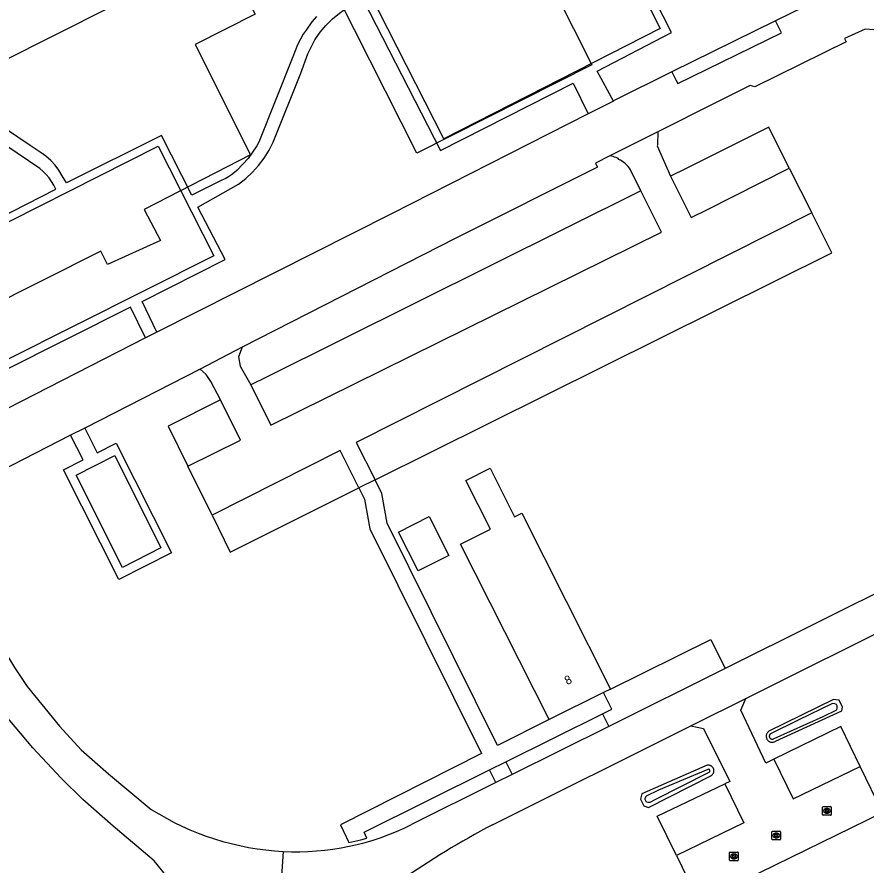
# Model space of a CAD drawing. Extents: x 158132 to 159658, y 385257 to 387209.
# Drawn here: x 159064.7 to 159162.7, y 386283.7 to 386381.6 of the extents above; entities that cross this region are included whole.
import ezdxf

# ---------------------------------------------------------------- set-up
doc = ezdxf.new("R2010")
doc.units = 0
for name, color, linetype in [('IMGEO_Groenvoorziening', 7, 'Continuous'), ('IMGEO_Kolk', 7, 'Continuous'), ('IMGEO_Pand', 7, 'Continuous'), ('IMGEO_Pand_nummerreeks', 7, 'Continuous'), ('IMGEO_Pand_vergunning_verleend', 7, 'Continuous'), ('IMGEO_Parkeervlak_halfverhard', 7, 'Continuous'), ('IMGEO_Parkeervlak_open', 7, 'Continuous'), ('IMGEO_Rijbaan_lokaal_gesloten', 7, 'Continuous'), ('IMGEO_Rijbaan_lokaal_open', 7, 'Continuous'), ('IMGEO_Voetpad_open', 7, 'Continuous'), ('IMGEO_Waterloop', 7, 'Continuous')]:
    doc.layers.add(name, color=color, linetype=linetype)

msp = doc.modelspace()

# ---------------------------------------------------------------- linework, layer by layer
at = {"layer": 'IMGEO_Groenvoorziening'}
for points in [[(159158.798, 386302.932), (159151.341, 386299.282), (159151.292, 386299.246), (159151.247, 386299.206), (159151.205, 386299.162), (159151.167, 386299.115), (159151.133, 386299.065), (159151.104, 386299.012), (159151.08, 386298.957), (159151.06, 386298.9), (159151.045, 386298.841), (159151.036, 386298.781), (159151.032, 386298.721), (159151.033, 386298.66), (159151.039, 386298.6), (159151.051, 386298.541), (159151.067, 386298.482), (159151.089, 386298.426), (159151.116, 386298.372), (159151.147, 386298.32), (159151.182, 386298.271), (159151.222, 386298.225), (159151.265, 386298.183), (159151.312, 386298.145), (159151.362, 386298.111), (159151.415, 386298.081), (159151.47, 386298.057), (159151.527, 386298.037), (159151.586, 386298.022), (159151.646, 386298.012), (159151.706, 386298.008), (159151.767, 386298.009), (159151.827, 386298.015), (159151.886, 386298.026), (159151.945, 386298.042), (159152.001, 386298.064), (159152.056, 386298.09), (159152.108, 386298.121), (159159.754, 386301.623), (159159.831, 386302.052), (159159.448, 386302.852), (159158.798, 386302.932)], [(159144.994, 386294.836), (159144.981, 386294.891), (159144.964, 386294.944), (159144.942, 386294.996), (159144.916, 386295.045), (159144.885, 386295.093), (159144.851, 386295.137), (159144.812, 386295.178), (159144.771, 386295.215), (159144.726, 386295.249), (159144.678, 386295.279), (159144.628, 386295.305), (159144.576, 386295.326), (159144.523, 386295.342), (159144.468, 386295.354), (159144.412, 386295.36), (159144.356, 386295.362), (159144.3, 386295.359), (159144.244, 386295.351), (159136.707, 386292.056), (159136.523, 386291.463), (159136.925, 386290.7), (159137.467, 386290.481), (159144.636, 386294.139), (159144.686, 386294.165), (159144.733, 386294.196), (159144.777, 386294.23), (159144.818, 386294.268), (159144.856, 386294.31), (159144.89, 386294.355), (159144.92, 386294.402), (159144.946, 386294.452), (159144.967, 386294.504), (159144.983, 386294.558), (159144.995, 386294.612), (159145.002, 386294.668), (159145.004, 386294.724), (159145.001, 386294.78), (159144.994, 386294.836)]]:
    msp.add_lwpolyline(points, dxfattribs=at)
at = {"layer": 'IMGEO_Kolk'}
for p, q in [((159157.534, 386289.676), (159157.534, 386290.528)), ((159157.609, 386290.602), (159158.461, 386290.602)), ((159158.022, 386290.382), (159158.047, 386290.382)), ((159158.535, 386290.528), (159158.535, 386289.676)), ((159158.461, 386289.602), (159157.609, 386289.602)), ((159158.045, 386289.822), (159158.02, 386289.822)), ((159151.694, 386286.836), (159151.694, 386287.688)), ((159151.769, 386287.762), (159152.621, 386287.762)), ((159152.182, 386287.542), (159152.207, 386287.542)), ((159152.695, 386287.688), (159152.695, 386286.836)), ((159152.621, 386286.762), (159151.769, 386286.762)), ((159152.205, 386286.982), (159152.18, 386286.982)), ((159146.813, 386284.434), (159146.813, 386285.286)), ((159146.888, 386285.36), (159147.74, 386285.36)), ((159147.324, 386284.58), (159147.299, 386284.58)), ((159147.301, 386285.14), (159147.326, 386285.14)), ((159147.814, 386285.286), (159147.814, 386284.434)), ((159147.74, 386284.36), (159146.888, 386284.36))]:
    msp.add_line(p, q, dxfattribs=at)
for points in [[(159157.534, 386289.676), (159157.534, 386290.528)], [(159157.609, 386290.602), (159158.461, 386290.602)], [(159158.535, 386290.528), (159158.535, 386289.676)], [(159158.461, 386289.602), (159157.609, 386289.602)], [(159157.855, 386290.302), (159157.978, 386290.302), (159157.978, 386290.151), (159158.108, 386290.302), (159158.272, 386290.302), (159158.126, 386290.151), (159158.279, 386289.902), (159158.127, 386289.902), (159158.042, 386290.066), (159157.978, 386289.999), (159157.978, 386289.902), (159157.855, 386289.902), (159157.855, 386290.302)], [(159151.694, 386286.836), (159151.694, 386287.688)], [(159151.769, 386287.762), (159152.621, 386287.762)], [(159152.015, 386287.462), (159152.138, 386287.462), (159152.138, 386287.311), (159152.268, 386287.462), (159152.432, 386287.462), (159152.286, 386287.311), (159152.439, 386287.062), (159152.287, 386287.062), (159152.202, 386287.226), (159152.138, 386287.159), (159152.138, 386287.062), (159152.015, 386287.062), (159152.015, 386287.462)], [(159152.695, 386287.688), (159152.695, 386286.836)], [(159152.621, 386286.762), (159151.769, 386286.762)], [(159146.813, 386284.434), (159146.813, 386285.286)], [(159146.888, 386285.36), (159147.74, 386285.36)], [(159147.134, 386285.06), (159147.257, 386285.06), (159147.257, 386284.909), (159147.387, 386285.06), (159147.551, 386285.06), (159147.405, 386284.909), (159147.558, 386284.66), (159147.406, 386284.66), (159147.321, 386284.824), (159147.257, 386284.757), (159147.257, 386284.66), (159147.134, 386284.66), (159147.134, 386285.06)], [(159147.814, 386285.286), (159147.814, 386284.434)], [(159147.74, 386284.36), (159146.888, 386284.36)]]:
    msp.add_lwpolyline(points, dxfattribs=at)
for centre, start, end in [((159157.611, 386290.526), 91.55205, 178.44795), ((159157.611, 386290.526), 91.55205, 178.44795), ((159158.459, 386290.526), 1.55205, 88.44795), ((159158.459, 386290.526), 1.55205, 88.44795), ((159157.611, 386289.678), 181.55205, 268.44795), ((159157.611, 386289.678), 181.55205, 268.44795), ((159158.459, 386289.678), 271.55205, 358.44795), ((159158.459, 386289.678), 271.55205, 358.44795), ((159151.771, 386287.686), 91.55205, 178.44795), ((159151.771, 386287.686), 91.55205, 178.44795), ((159152.619, 386287.686), 1.55205, 88.44795), ((159152.619, 386287.686), 1.55205, 88.44795), ((159151.771, 386286.838), 181.55205, 268.44795), ((159151.771, 386286.838), 181.55205, 268.44795), ((159152.619, 386286.838), 271.55205, 358.44795), ((159152.619, 386286.838), 271.55205, 358.44795), ((159146.89, 386285.284), 91.55205, 178.44795), ((159146.89, 386285.284), 91.55205, 178.44795), ((159147.738, 386285.284), 1.55205, 88.44795), ((159147.738, 386285.284), 1.55205, 88.44795), ((159146.89, 386284.436), 181.55205, 268.44795), ((159146.89, 386284.436), 181.55205, 268.44795), ((159147.738, 386284.436), 271.55205, 358.44795), ((159147.738, 386284.436), 271.55205, 358.44795)]:
    msp.add_arc(centre, 0.0765, start, end, dxfattribs=at)
for centre, major_axis, ratio, start_param, end_param in [((159158.021, 386290.102), (-0.387, 0.002), 0.722429, 4.712389, 7.853982), ((159158.046, 386290.102), (-0.39, 0.002), 0.717154, 1.570796, 4.712389), ((159152.181, 386287.262), (-0.387, 0.002), 0.722429, 4.712389, 7.853982), ((159152.206, 386287.262), (-0.39, 0.002), 0.717154, 1.570796, 4.712389), ((159147.3, 386284.86), (-0.387, 0.002), 0.722429, 4.712389, 7.853982), ((159147.325, 386284.86), (-0.39, 0.002), 0.717154, 1.570796, 4.712389)]:
    msp.add_ellipse(centre, major_axis=major_axis, ratio=ratio, start_param=start_param, end_param=end_param, dxfattribs=at)
at = {"layer": 'IMGEO_Pand'}
for points in [[(159075.958, 386331.045), (159081.256, 386320.404), (159076.815, 386318.132), (159071.496, 386328.786), (159075.958, 386331.045)], [(159126.002, 386300.637), (159115.808, 386320.841), (159119.244, 386322.574), (159116.412, 386328.188), (159119.201, 386329.595), (159122.033, 386323.981), (159122.863, 386324.4), (159133.085, 386304.138)], [(159114.449, 386319.54), (159110.896, 386317.747), (159108.63, 386322.237), (159112.184, 386324.031), (159114.449, 386319.54)], [(159133.085, 386304.138), (159132.291, 386303.745)], [(159132.291, 386303.745), (159126.002, 386300.637)]]:
    msp.add_lwpolyline(points, dxfattribs=at)
at = {"layer": 'IMGEO_Pand_vergunning_verleend'}
msp.add_lwpolyline([(159050.566, 386368.036), (159057.316, 386371.439), (159056.434, 386373.19), (159088.099, 386389.152), (159085.805, 386393.704), (159116.592, 386409.224), (159123.517, 386395.487), (159125.076, 386396.273), (159128.071, 386390.332), (159124.613, 386388.589), (159130.927, 386376.065), (159110.742, 386365.89), (159098.147, 386390.876), (159089.73, 386386.633), (159092.108, 386381.915), (159085.183, 386378.425), (159091.591, 386365.714), (159079.324, 386359.397), (159081.204, 386355.823), (159075.094, 386353.069), (159074.314, 386354.616), (159060.772, 386347.79), (159050.566, 386368.036)], dxfattribs=at)
at = {"layer": 'IMGEO_Parkeervlak_halfverhard'}
for points in [[(159153.697, 386364.175), (159151.323, 386368.887), (159141.789, 386364.145), (159140.014, 386363.262)], [(159136.589, 386361.558), (159093.441, 386340.095), (159091.613, 386339.186)], [(159105.953, 386328.242), (159158.608, 386354.428), (159156.297, 386359.015)], [(159088.141, 386337.458), (159082.079, 386334.443), (159084.365, 386329.818)], [(159087.154, 386324.178), (159089.251, 386319.936), (159104.088, 386327.315)]]:
    msp.add_lwpolyline(points, dxfattribs=at)
at = {"layer": 'IMGEO_Parkeervlak_open'}
for points in [[(159161.883, 386295.226), (159159.646, 386299.844), (159151.929, 386296.073)], [(159140.694, 386284.963), (159138.479, 386289.495), (159146.258, 386293.231)]]:
    msp.add_lwpolyline(points, dxfattribs=at)
at = {"layer": 'IMGEO_Rijbaan_lokaal_gesloten'}
for points in [[(159160.679, 386385.483), (159159.095, 386384.711), (159156.975, 386383.586), (159152.098, 386381.168)], [(159140.172, 386375.255), (159140.617, 386374.368), (159140.838, 386373.928), (159152.778, 386379.783), (159152.098, 386381.168)], [(159163.452, 386380.131), (159162.434, 386380.179), (159160.052, 386379.107), (159160.256, 386378.722), (159149.707, 386373.549), (159149.172, 386373.703), (159145.189, 386371.704), (159138.555, 386368.375)], [(159140.172, 386375.255), (159133.433, 386371.914), (159133.41, 386371.902)], [(159133.41, 386371.902), (159130.505, 386370.426)], [(159130.505, 386370.426), (159107.817, 386358.895), (159080.782, 386345.286)], [(159138.555, 386368.375), (159133.011, 386365.593)], [(159133.011, 386365.593), (159131.347, 386364.73), (159131.513, 386364.412), (159131.574, 386364.295), (159115.248, 386356.119), (159090.616, 386343.54)], [(159080.782, 386345.286), (159079.47, 386344.616)], [(159079.47, 386344.616), (159061.863, 386335.619), (159057.491, 386333.552), (159057.754, 386333.009), (159056.795, 386332.597), (159056.135, 386332.455), (159055.464, 386332.371), (159054.789, 386332.347), (159054.115, 386332.381), (159053.446, 386332.474), (159052.787, 386332.626), (159052.145, 386332.834), (159051.523, 386333.098), (159050.927, 386333.415), (159050.36, 386333.783), (159049.828, 386334.199), (159049.335, 386334.66), (159048.883, 386335.163), (159048.542, 386335.617)], [(159090.616, 386343.54), (159085.768, 386341.008)], [(159085.768, 386341.008), (159072.465, 386334.219)], [(159072.465, 386334.219), (159070.847, 386333.393)], [(159070.847, 386333.393), (159061.295, 386328.518), (159060.937, 386329.18), (159060.892, 386329.157)], [(159105.953, 386328.242), (159104.088, 386327.315)], [(159126.002, 386300.637), (159120.07, 386297.644), (159107.337, 386323.246), (159106.738, 386326.663), (159105.953, 386328.242)], [(159104.088, 386327.315), (159104.739, 386326.006), (159105.338, 386322.589), (159118.21, 386296.706), (159101.95, 386288.501), (159102.935, 386286.444), (159103.626, 386286.599), (159104.313, 386286.771), (159104.996, 386286.96), (159104.695, 386287.635), (159119.145, 386294.827)], [(159187.744, 386327.14), (159146.313, 386306.52)], [(159148.667, 386303.059), (159186.019, 386321.678), (159190.748, 386323.367), (159191.885, 386323.216)], [(159057.062, 386320.945), (159063.133, 386308.664), (159064.373, 386306.618), (159065.843, 386304.447), (159069.55, 386299.848), (159072.072, 386297.131), (159075.195, 386294.366), (159080.133, 386290.273)], [(159083.086, 386281.447), (159081.827, 386282.687), (159080.46, 386284.342), (159075.757, 386288.34), (159072.25, 386291.429), (159069.75, 386293.857), (159066.469, 386297.371), (159062.371, 386302.202), (159058.593, 386308.797), (159053.255, 386319.337)], [(159146.313, 386306.52), (159132.873, 386299.831)], [(159132.148, 386301.298), (159133.233, 386301.839), (159132.291, 386303.745)], [(159142.345, 386299.908), (159143.713, 386300.59), (159147.686, 386302.57), (159148.667, 386303.059)], [(159121.01, 386295.755), (159132.148, 386301.298)], [(159119.464, 386288.503), (159142.345, 386299.908)], [(159132.873, 386299.831), (159121.739, 386294.29)], [(159119.145, 386294.827), (159121.01, 386295.755)], [(159121.739, 386294.29), (159119.874, 386293.362)], [(159119.874, 386293.362), (159110.158, 386288.526)], [(159095.353, 386285.418), (159094.463, 386272.209)]]:
    msp.add_lwpolyline(points, dxfattribs=at)
for centre, radius, start, end in [((159097.116, 386317.23), 31.861, 237.78851, 266.82735), ((159096.795, 386315.367), 29.983, 267.2441, 296.46767), ((159168.468, 386195.847), 104.817, 117.87331, 124.66655)]:
    msp.add_arc(centre, radius, start, end, dxfattribs=at)
at = {"layer": 'IMGEO_Rijbaan_lokaal_open'}
for points in [[(159152.098, 386381.168), (159140.172, 386375.255)], [(159138.555, 386368.375), (159138.49, 386366.831), (159138.482, 386366.756), (159140.014, 386363.262)], [(159136.589, 386361.558), (159135.376, 386363.966), (159135.257, 386364.163), (159135.122, 386364.349), (159134.971, 386364.524), (159134.806, 386364.685), (159134.629, 386364.831), (159134.34, 386365.019), (159134.239, 386365.077), (159134.181, 386365.104), (159134.03, 386365.174), (159133.971, 386365.278), (159133.886, 386365.323), (159133.721, 386365.397), (159133.549, 386365.457), (159133.373, 386365.508), (159133.193, 386365.552), (159133.011, 386365.593)], [(159140.014, 386363.262), (159142.374, 386358.488), (159144.188, 386359.384), (159153.697, 386364.175)], [(159153.697, 386364.175), (159156.297, 386359.015)], [(159091.613, 386339.186), (159093.911, 386334.537), (159138.944, 386356.793), (159136.589, 386361.558)], [(159156.297, 386359.015), (159103.78, 386332.554), (159105.953, 386328.242)], [(159090.616, 386343.54), (159090.185, 386342.439), (159090.393, 386341.357), (159091.613, 386339.186)], [(159088.141, 386337.458), (159087.019, 386339.578), (159086.465, 386340.375), (159085.768, 386341.008)], [(159084.365, 386329.818), (159090.434, 386332.819), (159088.141, 386337.458)], [(159104.088, 386327.315), (159101.92, 386331.617), (159087.154, 386324.178)], [(159087.154, 386324.178), (159084.365, 386329.818)], [(159151.929, 386296.073), (159150.98, 386295.609), (159148.09, 386301.717), (159148.667, 386303.059)], [(159142.345, 386299.908), (159143.804, 386299.576), (159146.826, 386293.504), (159146.258, 386293.231)], [(159151.929, 386296.073), (159154.152, 386291.482), (159161.883, 386295.226)], [(159164.449, 386289.929), (159161.883, 386295.226)], [(159146.258, 386293.231), (159148.444, 386288.717), (159140.694, 386284.963)], [(159143.317, 386279.598), (159164.449, 386289.929)], [(159140.694, 386284.963), (159143.317, 386279.598)]]:
    msp.add_lwpolyline(points, dxfattribs=at)
at = {"layer": 'IMGEO_Voetpad_open'}
for points in [[(159133.41, 386371.902), (159131.529, 386375.366), (159140.13, 386379.794), (159130.619, 386398.422)], [(159116.336, 386390.137), (159130.182, 386397.221), (159138.808, 386380.26), (159113.882, 386367.548), (159105.257, 386384.482), (159116.336, 386390.137)], [(159080.782, 386345.286), (159079.09, 386348.8), (159088.644, 386353.634), (159085.519, 386359.692), (159090.211, 386362.312), (159091.043, 386362.969), (159091.815, 386363.694), (159092.522, 386364.484), (159093.159, 386365.33), (159093.721, 386366.229), (159094.203, 386367.172), (159097.369, 386375.129), (159098.208, 386377.35), (159098.998, 386378.976), (159099.604, 386379.832), (159100.282, 386380.632), (159101.027, 386381.369), (159101.834, 386382.04), (159102.696, 386382.637), (159103.606, 386383.158), (159104.558, 386383.597), (159113.487, 386366.21), (159128.77, 386373.974), (159130.505, 386370.426)], [(159099.19, 386381.647), (159098.647, 386381.044), (159097.987, 386380.087), (159097.641, 386379.603), (159097.33, 386379.036), (159097.015, 386378.372), (159096.448, 386377.01), (159092.558, 386367.17), (159092.329, 386366.736), (159091.329, 386365.29), (159090.038, 386363.954), (159089.731, 386363.663), (159089.4, 386363.398), (159089.049, 386363.162), (159088.679, 386362.955), (159088.293, 386362.781), (159084.835, 386361.067), (159081.319, 386367.944), (159070.352, 386362.468), (159069.879, 386363.289), (159069.495, 386363.924), (159069.052, 386364.52), (159068.553, 386365.069), (159068.004, 386365.568), (159067.459, 386365.935), (159066.191, 386366.784), (159064.752, 386367.755), (159063.326, 386368.695)], [(159055.815, 386354.967), (159069.132, 386361.769), (159068.908, 386362.218), (159068.649, 386362.647), (159068.356, 386363.054), (159068.031, 386363.436), (159067.677, 386363.791), (159067.295, 386364.116), (159060.592, 386368.622)], [(159057.023, 386354.632), (159080.924, 386366.724), (159087.338, 386354.081), (159063.424, 386342.05), (159057.023, 386354.632)], [(159079.47, 386344.616), (159077.738, 386348.161), (159062.977, 386340.742)], [(159072.465, 386334.219), (159073.901, 386331.373), (159076.083, 386332.475), (159082.461, 386319.846), (159076.384, 386316.777), (159070.007, 386329.407), (159072.281, 386330.555), (159070.847, 386333.393)], [(159133.085, 386304.138), (159144.653, 386309.856), (159146.313, 386306.52)], [(159132.148, 386301.298), (159132.873, 386299.831)], [(159121.01, 386295.755), (159121.739, 386294.29)], [(159119.874, 386293.362), (159119.145, 386294.827)]]:
    msp.add_lwpolyline(points, dxfattribs=at)
at = {"layer": 'IMGEO_Waterloop'}
for points in [[(159159.193, 386301.747), (159159.219, 386301.993), (159159.205, 386302.192), (159159.123, 386302.343), (159158.96, 386302.447), (159158.666, 386302.475), (159154.732, 386300.573), (159151.526, 386298.979), (159151.515, 386298.97), (159151.493, 386298.951), (159151.471, 386298.928), (159151.452, 386298.904), (159151.435, 386298.88), (159151.422, 386298.856), (159151.41, 386298.827), (159151.399, 386298.798), (159151.393, 386298.771), (159151.388, 386298.743), (159151.386, 386298.712), (159151.387, 386298.681), (159151.39, 386298.653), (159151.396, 386298.623), (159151.404, 386298.593), (159151.413, 386298.57), (159151.427, 386298.542), (159151.444, 386298.514), (159151.46, 386298.491), (159151.48, 386298.468), (159151.501, 386298.448), (159151.523, 386298.43), (159151.549, 386298.412), (159151.573, 386298.398), (159151.6, 386298.387), (159151.629, 386298.376), (159151.659, 386298.369), (159151.687, 386298.364), (159151.715, 386298.362), (159151.746, 386298.363), (159151.777, 386298.366), (159151.807, 386298.372), (159151.834, 386298.379), (159151.86, 386298.389), (159151.889, 386298.403), (159151.944, 386298.436), (159157.606, 386300.986), (159159.193, 386301.747)], [(159144.432, 386294.536), (159138.209, 386291.377), (159137.637, 386291.076), (159137.369, 386291.056), (159137.251, 386291.092), (159137.074, 386291.422), (159137.074, 386291.572), (159137.227, 386291.818), (159138.657, 386292.539), (159144.359, 386294.915)]]:
    msp.add_lwpolyline(points, dxfattribs=at)
msp.add_arc((159144.36, 386294.719), 0.196, 291.40141, 90.40328, dxfattribs=at)

# ---------------------------------------------------------------- texts
at = {"layer": 'IMGEO_Pand_nummerreeks'}
msp.add_text('8', height=1, rotation=26.57951, dxfattribs=at).set_placement((159128.08, 386304.584))

doc.saveas('drawing.dxf')
